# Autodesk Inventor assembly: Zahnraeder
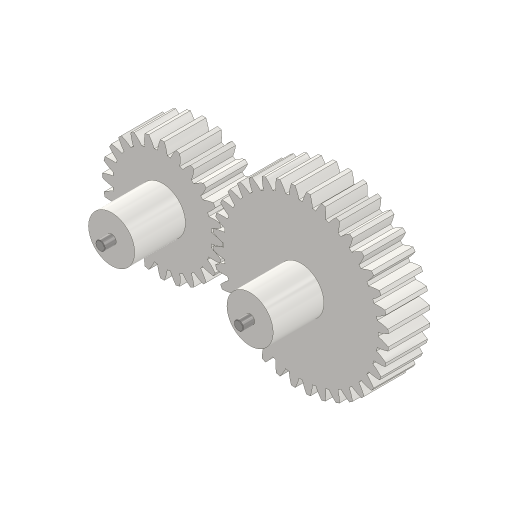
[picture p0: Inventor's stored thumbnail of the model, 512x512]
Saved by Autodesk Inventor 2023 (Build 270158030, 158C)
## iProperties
Created: 2022-09
Part Number: Zahnraeder
Document SubType Name: Assembly
Designer: Christoph Steinmann
Author: Christoph Steinmann
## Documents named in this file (4)
- D:\Lehre\CAD\Komplex2\Zahnraeder.iam
- D:\Lehre\CAD\Komplex2\Achse.ipt
- D:\Lehre\CAD\Komplex2\Stirnzahnrad11.ipt
- D:\Lehre\CAD\Komplex2\Stirnzahnrad21.ipt
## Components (4 placed, 3 different names)
1. Achse:1 — Fluchtend:1, Passend:3, Fluchtend:2, Passend:5, Passend:6, Passend:8
2. Achse:2 — Fluchtend:1, Passend:4, Fluchtend:3, Passend:5, Passend:7, Passend:9
3. Stirnzahnrad1:1 — Passend:3, Fluchtend:2, Drehung:1, Passend:6
4. Stirnzahnrad2:1 — Passend:4, Fluchtend:3, Drehung:1, Passend:7
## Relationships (11: Mate 7, Flush 3, RelateRotation 1)
- Fluchtend:1 [Flush]: Achse:1 ↔ Achse:2
- Passend:3 [Mate]: Achse:1 ↔ Stirnzahnrad1:1
- Fluchtend:2 [Flush]: Achse:1 ↔ Stirnzahnrad1:1
- Passend:4 [Mate]: Achse:2 ↔ Stirnzahnrad2:1
- Fluchtend:3 [Flush]: Achse:2 ↔ Stirnzahnrad2:1
- Drehung:1 [RelateRotation]: Stirnzahnrad1:1 ↔ Stirnzahnrad2:1
- Passend:5 [Mate]: Achse:1 ↔ Achse:2
- Passend:6 [Mate]: Achse:1 ↔ Stirnzahnrad1:1
- Passend:7 [Mate]: Achse:2 ↔ Stirnzahnrad2:1
- Passend:8 [Mate]: Achse:1
- Passend:9 [Mate]: Achse:2
